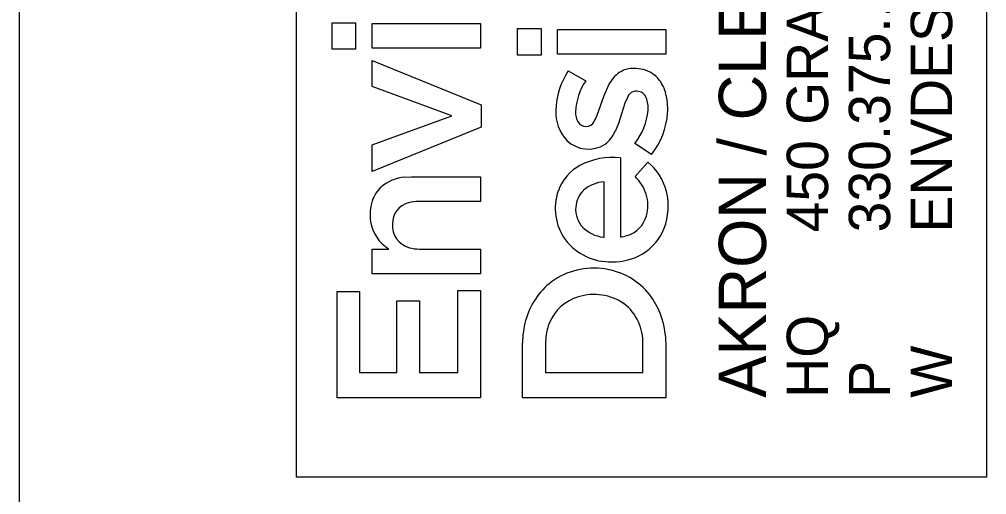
# Model space of a CAD drawing. Extents: x -0.3 to 41.5, y 0 to 22.
# Drawn here: x 32 to 33.166, y 2.521 to 3.094 of the extents above; entities that cross this region are included whole.
import ezdxf

# ---------------------------------------------------------------- set-up
doc = ezdxf.new("R2010")
doc.units = 0
for name, color, linetype in [('GM_X_Adjacent_County', 7, 'Continuous'), ('SH_Cut_Line', 7, 'Continuous'), ('SH_Data', 7, 'Continuous')]:
    doc.layers.add(name, color=color, linetype=linetype)

msp = doc.modelspace()

# ---------------------------------------------------------------- linework, layer by layer
at = {"layer": 'GM_X_Adjacent_County'}
msp.add_lwpolyline([(32.334, 2.5421), (32.334, 4.3266), (33.166, 4.3266), (33.166, 2.5421)], close=True, dxfattribs=at)
at = {"layer": 'SH_Cut_Line'}
for p, q in [((32.3771, 3.0582), (32.3771, 3.0903)), ((32.3771, 3.0903), (32.4054, 3.0903)), ((32.4054, 3.0903), (32.4054, 3.0582)), ((32.4254, 3.0594), (32.4254, 3.0893)), ((32.4254, 3.0893), (32.5557, 3.0893)), ((32.5557, 3.0893), (32.5557, 3.0594)), ((32.6005, 3.0511), (32.6005, 3.0832)), ((32.6005, 3.0832), (32.6289, 3.0832)), ((32.6289, 3.0832), (32.6289, 3.0511)), ((32.6489, 3.0523), (32.6489, 3.0822)), ((32.6489, 3.0822), (32.7792, 3.0822)), ((32.7792, 3.0822), (32.7792, 3.0523)), ((32.4054, 3.0582), (32.3771, 3.0582)), ((32.5557, 3.0594), (32.4254, 3.0594)), ((32.4254, 3.0133), (32.4254, 3.0446)), ((32.4254, 3.0446), (32.5567, 2.9913)), ((32.6289, 3.0511), (32.6005, 3.0511)), ((32.7792, 3.0523), (32.6489, 3.0523)), ((32.6615, 3.0321), (32.6827, 3.0203)), ((32.5212, 2.978), (32.4254, 3.0133)), ((32.7048, 3.0026), (32.7104, 3.0153)), ((32.6967, 2.9787), (32.7048, 3.0026)), ((32.7334, 3.001), (32.7298, 2.9933)), ((32.5567, 2.9913), (32.5567, 2.9644)), ((32.7298, 2.9933), (32.7221, 2.9688)), ((32.4254, 2.9429), (32.5212, 2.978)), ((32.693, 2.9712), (32.6967, 2.9787)), ((32.5567, 2.9644), (32.4254, 2.9109)), ((32.7221, 2.9688), (32.7182, 2.9592)), ((32.4254, 2.9109), (32.4254, 2.9429)), ((32.7621, 2.9314), (32.742, 2.9447)), ((32.7245, 2.9275), (32.7246, 2.8319)), ((32.7423, 2.9046), (32.7577, 2.922)), ((32.4644, 2.904), (32.4729, 2.9044)), ((32.4729, 2.9044), (32.5557, 2.9044)), ((32.5557, 2.9044), (32.5557, 2.8746)), ((32.7049, 2.8318), (32.7049, 2.8983)), ((32.5557, 2.8746), (32.4814, 2.8746)), ((32.7036, 2.8317), (32.7049, 2.8318)), ((32.4254, 2.7875), (32.4254, 2.8173)), ((32.4254, 2.8173), (32.4455, 2.8173)), ((32.4822, 2.8173), (32.5557, 2.8173)), ((32.5557, 2.8173), (32.5557, 2.7876)), ((32.5557, 2.7876), (32.4254, 2.7875)), ((32.383, 2.6379), (32.383, 2.766)), ((32.383, 2.766), (32.4101, 2.766)), ((32.4101, 2.766), (32.4101, 2.6683)), ((32.5286, 2.6683), (32.5286, 2.7672)), ((32.5286, 2.7672), (32.5557, 2.7672)), ((32.5557, 2.7672), (32.5557, 2.6379)), ((32.455, 2.6683), (32.455, 2.7549)), ((32.455, 2.7549), (32.4822, 2.7549)), ((32.4822, 2.7549), (32.4822, 2.6683)), ((32.6347, 2.7118), (32.6341, 2.7023)), ((32.7785, 2.715), (32.7792, 2.7021)), ((32.6064, 2.638), (32.6064, 2.704)), ((32.6341, 2.7023), (32.6341, 2.6684)), ((32.7515, 2.6683), (32.7515, 2.7024)), ((32.7792, 2.7021), (32.7792, 2.638)), ((32.4101, 2.6683), (32.455, 2.6683)), ((32.4822, 2.6683), (32.5286, 2.6683)), ((32.6341, 2.6684), (32.7515, 2.6683)), ((32.5557, 2.6379), (32.383, 2.6379)), ((32.7792, 2.638), (32.6064, 2.638))]:
    msp.add_line(p, q, dxfattribs=at)
for points in [[(32.3771, 3.0582), (32.3771, 3.0903), (32.4054, 3.0903), (32.4054, 3.0582)], [(32.4254, 3.0594), (32.4254, 3.0893), (32.5557, 3.0893), (32.5557, 3.0594)], [(32.6005, 3.0511), (32.6005, 3.0832), (32.6289, 3.0832), (32.6289, 3.0511)], [(32.6489, 3.0523), (32.6489, 3.0822), (32.7792, 3.0822), (32.7792, 3.0523)], [(32.4254, 2.9109), (32.4254, 2.9429), (32.5212, 2.978), (32.4254, 3.0133), (32.4254, 3.0446), (32.5567, 2.9913), (32.5567, 2.9644)], [(32.383, 2.6379), (32.383, 2.766), (32.4101, 2.766), (32.4101, 2.6683), (32.455, 2.6683), (32.455, 2.7549), (32.4822, 2.7549), (32.4822, 2.6683), (32.5286, 2.6683), (32.5286, 2.7672), (32.5557, 2.7672), (32.5557, 2.6379)]]:
    msp.add_lwpolyline(points, close=True, dxfattribs=at)
for points in [[(32.6615, 3.0321), (32.6827, 3.0203)], [(32.693, 2.9712), (32.6967, 2.9787), (32.7048, 3.0026), (32.7104, 3.0153)], [(32.7334, 3.001), (32.7298, 2.9933), (32.7221, 2.9688), (32.7182, 2.9592)], [(32.7621, 2.9314), (32.742, 2.9447)], [(32.7245, 2.9275), (32.7246, 2.8319)], [(32.7423, 2.9046), (32.7577, 2.922)], [(32.4644, 2.904), (32.4729, 2.9044), (32.5557, 2.9044), (32.5557, 2.8746), (32.4814, 2.8746)], [(32.7036, 2.8317), (32.7049, 2.8318), (32.7049, 2.8983)], [(32.4254, 2.7875), (32.4254, 2.8173), (32.4455, 2.8173)], [(32.4822, 2.8173), (32.5557, 2.8173), (32.5557, 2.7876), (32.4254, 2.7875)], [(32.7785, 2.715), (32.7792, 2.7021), (32.7792, 2.638), (32.6064, 2.638)], [(32.6347, 2.7118), (32.6341, 2.7023), (32.6341, 2.6684), (32.7515, 2.6683), (32.7515, 2.7024)], [(32.6064, 2.638), (32.6064, 2.704)]]:
    msp.add_lwpolyline(points, dxfattribs=at)
for centre, radius, start, end in [((32.7364, 2.9826), 0.0897, 146.531, 178.7571), ((32.7364, 2.9826), 0.0897, 146.531, 178.7571), ((32.7406, 3.0026), 0.0326, 80.1719, 122.5197), ((32.7406, 3.0026), 0.0326, 80.1719, 122.5197), ((32.7428, 2.9982), 0.0367, 47.7934, 84.6892), ((32.7428, 2.9982), 0.0367, 47.7934, 84.6892), ((32.7452, 2.9789), 0.0749, 146.5112, 176.9101), ((32.7452, 2.9789), 0.0749, 146.5112, 176.9101), ((32.7466, 2.9971), 0.0405, 125.5118, 153.4159), ((32.7466, 2.9971), 0.0405, 125.5118, 153.4159), ((32.7379, 2.9946), 0.0427, 14.9966, 46.2063), ((32.7379, 2.9946), 0.0427, 14.9966, 46.2063), ((32.7438, 2.9963), 0.0114, 76.6609, 155.7053), ((32.7438, 2.9963), 0.0114, 76.6609, 155.7053), ((32.744, 2.9951), 0.0126, 21.5098, 78.5262), ((32.744, 2.9951), 0.0126, 21.5098, 78.5262), ((32.7259, 2.9877), 0.0321, 354.5726, 22.068), ((32.7259, 2.9877), 0.0321, 354.5726, 22.068), ((32.7104, 2.9867), 0.0712, 355.8306, 15.3914), ((32.7104, 2.9867), 0.0712, 355.8306, 15.3914), ((32.6967, 2.9824), 0.0501, 177.5366, 222.7932), ((32.6967, 2.9824), 0.0501, 177.5366, 222.7932), ((32.6931, 2.9823), 0.0228, 178.4747, 211.0868), ((32.6931, 2.9823), 0.0228, 178.4747, 211.0868), ((32.6825, 2.9915), 0.0757, 321.811, 354.7969), ((32.6825, 2.9915), 0.0757, 321.811, 354.7969), ((32.6895, 2.9882), 0.0922, 321.9777, 355.8738), ((32.6895, 2.9882), 0.0922, 321.9777, 355.8738), ((32.6833, 2.9767), 0.0115, 212.2368, 268.3777), ((32.6833, 2.9767), 0.0115, 212.2368, 268.3777), ((32.6834, 2.9759), 0.0107, 267.716, 333.7337), ((32.6834, 2.9759), 0.0107, 267.716, 333.7337), ((32.681, 2.9758), 0.0408, 308.0877, 335.9874), ((32.681, 2.9758), 0.0408, 308.0877, 335.9874), ((32.686, 2.9753), 0.0375, 225.9854, 302.4797), ((32.686, 2.9753), 0.0375, 225.9854, 302.4797), ((32.7152, 2.8441), 0.0838, 83.615, 118.2876), ((32.7152, 2.8441), 0.0838, 83.615, 118.2876), ((32.7024, 2.8691), 0.0558, 118.8308, 160.6244), ((32.7024, 2.8691), 0.0558, 118.8308, 160.6244), ((32.7174, 2.8717), 0.0644, 13.5336, 51.3615), ((32.7174, 2.8717), 0.0644, 13.5336, 51.3615), ((32.4687, 2.8543), 0.0499, 94.9696, 130.2225), ((32.4687, 2.8543), 0.0499, 94.9696, 130.2225), ((32.7038, 2.8656), 0.0549, 19.0357, 45.4406), ((32.7038, 2.8656), 0.0549, 19.0357, 45.4406), ((32.4635, 2.8626), 0.0402, 132.2219, 161.6818), ((32.4635, 2.8626), 0.0402, 132.2219, 161.6818), ((32.7079, 2.8561), 0.0424, 94.008, 130.8817), ((32.7079, 2.8561), 0.0424, 94.008, 130.8817), ((32.7104, 2.8661), 0.0644, 160.5201, 215.7831), ((32.7104, 2.8661), 0.0644, 160.5201, 215.7831), ((32.7005, 2.8663), 0.0298, 132.9851, 177.179), ((32.7005, 2.8663), 0.0298, 132.9851, 177.179), ((32.7107, 2.8697), 0.047, 344.6059, 17.007), ((32.7107, 2.8697), 0.047, 344.6059, 17.007), ((32.7064, 2.8692), 0.0758, 339.3542, 13.3785), ((32.7064, 2.8692), 0.0758, 339.3542, 13.3785), ((32.4787, 2.8582), 0.056, 162.2736, 187.7919), ((32.4787, 2.8582), 0.056, 162.2736, 187.7919), ((32.4748, 2.8487), 0.025, 103.6865, 182.2187), ((32.4748, 2.8487), 0.025, 103.6865, 182.2187), ((32.4811, 2.8286), 0.046, 89.6049, 105.3284), ((32.4811, 2.8286), 0.046, 89.6049, 105.3284), ((32.7017, 2.865), 0.0311, 175.0013, 223.283), ((32.7017, 2.865), 0.0311, 175.0013, 223.283), ((32.7224, 2.8671), 0.035, 288.0077, 343.5508), ((32.7224, 2.8671), 0.035, 288.0077, 343.5508), ((32.4703, 2.858), 0.0476, 188.962, 238.7037), ((32.4703, 2.858), 0.0476, 188.962, 238.7037), ((32.4773, 2.8456), 0.0276, 175.5854, 255.1439), ((32.4773, 2.8456), 0.0276, 175.5854, 255.1439), ((32.7089, 2.8736), 0.0423, 225.0619, 262.7974), ((32.7089, 2.8736), 0.0423, 225.0619, 262.7974), ((32.7247, 2.8522), 0.0202, 269.7003, 294.8711), ((32.7247, 2.8522), 0.0202, 269.7003, 294.8711), ((32.7189, 2.8652), 0.0626, 300.9427, 338.7323), ((32.7189, 2.8652), 0.0626, 300.9427, 338.7323), ((32.7125, 2.8705), 0.0687, 217.7452, 271.6543), ((32.7125, 2.8705), 0.0687, 217.7452, 271.6543), ((32.4818, 2.8595), 0.0422, 254.0916, 270.5284), ((32.4818, 2.8595), 0.0422, 254.0916, 270.5284), ((32.7155, 2.8724), 0.0706, 269.2048, 300.3341), ((32.7155, 2.8724), 0.0706, 269.2048, 300.3341), ((32.6923, 2.7079), 0.0864, 81.194, 125.9984), ((32.6923, 2.7079), 0.0864, 81.194, 125.9984), ((32.6946, 2.7113), 0.0827, 37.8521, 82.402), ((32.6946, 2.7113), 0.0827, 37.8521, 82.402), ((32.6939, 2.7089), 0.0865, 127.2362, 165.148), ((32.6939, 2.7089), 0.0865, 127.2362, 165.148), ((32.6889, 2.7078), 0.054, 106.1881, 157.3861), ((32.6889, 2.7078), 0.054, 106.1881, 157.3861), ((32.6928, 2.6986), 0.0639, 55.6727, 107.2093), ((32.6928, 2.6986), 0.0639, 55.6727, 107.2093), ((32.6859, 2.7057), 0.0931, 5.7333, 37.304), ((32.6859, 2.7057), 0.0931, 5.7333, 37.304), ((32.6929, 2.705), 0.0587, 357.4662, 52.2665), ((32.6929, 2.705), 0.0587, 357.4662, 52.2665), ((32.7143, 2.7028), 0.1078, 164.7861, 179.3704), ((32.7143, 2.7028), 0.1078, 164.7861, 179.3704), ((32.6983, 2.7039), 0.0641, 157.3571, 172.9275), ((32.6983, 2.7039), 0.0641, 157.3571, 172.9275)]:
    msp.add_arc(centre, radius, start, end, dxfattribs=at)
at = {"layer": 'SH_Data'}
msp.add_line((32, 0.5), (32, 21.5), dxfattribs=at)

# ---------------------------------------------------------------- texts
at = {"layer": 'SH_Cut_Line'}
for s, height, p in [('450 GRANT ST., AKRON, OH  44311', 0.049846, (32.9749, 2.8374)), ('AKRON / CLEVELAND / COLUMBUS', 0.056969, (32.9001, 2.638)), ('ENVDESIGNGROUP.COM', 0.049846, (33.1244, 2.8374)), ('330.375.1390', 0.049846, (33.0497, 2.8374)), ('HQ ', 0.04985, (32.9749, 2.638)), ('W', 0.0498, (33.1244, 2.638)), ('P', 0.0498, (33.0497, 2.638))]:
    msp.add_text(s, height=height, rotation=90, dxfattribs=at).set_placement(p)

doc.saveas('drawing.dxf')
